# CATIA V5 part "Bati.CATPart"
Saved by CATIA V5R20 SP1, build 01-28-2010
Part number: Bati
Bounding box of the stored display mesh (mm): x -45 to 45, y 0 to 30, z 0 to 40
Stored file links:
  F:\Pro\Emplois\1_Chercheur\ThinkMOTION\MMS\MMS_GR1\abruchon\Catia\Bati.CATPart
  F:\Pro\Emplois\1_Chercheur\ThinkMOTION\MMS\MMS_GR1\abruchon\Catia\Vibrato.CATProduct
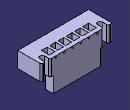
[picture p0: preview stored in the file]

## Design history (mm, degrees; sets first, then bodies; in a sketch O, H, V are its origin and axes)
Set1
  Plane1 to Plane7: linked copy from another document
  Point1: linked copy from another document
  Line1: linked copy from another document
  Line2: linked copy from another document
Body1 (main body)
  Sketch1 on xy-plane, origin (0, 0, 0), H (1, 0, 0), V (0, 1, 0)
    line L1 (-45, 30) -> (45, 30)
    line L2 (45, 30) -> (45, 0)
    line L3 (45, 0) -> (-45, 0)
    line L4 (-45, 0) -> (-45, 30)
    reference intersected line E1 through (0, 30) direction (-1, 0) from Plane1
    reference intersected line E2 through (45, 0) direction (0, 1) from Plane2
    reference intersected line E3 through (-45, 0) direction (0, 1) from Plane3
    reference intersected line E4 through (0, 0) direction (-1, 0) from Plane4
    distance E1 L1 = 0
    distance L2 E2 = 0
    distance E3 L4 = 0
    distance E4 L3 = 0
    horizontal: L1 H, L3 H
    vertical: L2 V, L4 V
  Pad1: profile Sketch1, direction (0, 0, 1), up to Plane5
  Sketch2 on face of Pad1 from Sketch1.L1, origin (0, 30, 0), H (-1, 0, 0), V (0, 0, 1)
    line L1 (-45, 20) -> (-30, 20)
    line L2 (-30, 20) -> (-30, -30)
    line L3 (-30, -30) -> (-45, -30)
    line L4 (-45, -30) -> (-45, 20)
    reference intersected line E1 through (-45, 0) direction (0, -1) from Plane2
    reference intersected line E2 through (-30, 0) direction (0, -1) from Plane6
    point P5 (30, 20)
    line L5 (30, 20) -> (45, 20)
    line L6 (45, 20) -> (45, -30)
    line L7 (45, -30) -> (30, -30)
    line L8 (30, -30) -> (30, 20)
    reference intersected line E3 through (30, 0) direction (0, -1) from Plane7
    reference intersected line E4 through (45, 0) direction (0, -1) from Plane3
    reference projected line E5 (45, 40) -> (-45, 40) from edge [end face of Pad1 | face of Pad1 from Sketch1.L1]
    distance E1 L4 = 0
    distance E2 L2 = 0
    distance E3 L8 = 0
    distance L6 E4 = 0
    distance E5 L5 = 20
    horizontal: L1 H, L3 H, L5 H, L7 H
    vertical: L2 V, L4 V, L6 V, L8 V
    coincidence: P5 L1
  Pocket1: profile Sketch2, direction (0, -1, 0), through (limit type 6)
  Sketch3 on face of Pad1 from Sketch1.L2, origin (45, 0, 0), H (0, 1, 0), V (0, 0, 1)
    line L1 (0, 34.0003) -> (0, 36)
    point P1 (0, 34.0003)
    point P2 (0, 36)
    line L2 (0, 36) -> (1, 35)
    point P3 (1, 35)
    line L3 (0, 34.0003) -> (1, 35)
    reference projected point E1 (1, 35) from Point1
    reference projected line E2 (0, 40) -> (30, 40) from edge [face of Pad1 from Sketch1.L2 | end face of Pad1]
    distance E1 P3 = 0
    distance P2 E2 = 4
    length L3 = 1.414
    length L2 = 1.4142
    coincidence: P1 V
    vertical: L1 V
  Slot1: profile Sketch3, centre curve Line1
  Sketch4 on face of Pad1 from Sketch1.L3, origin (0, 0, 0), H (1, 0, 0), V (0, 0, 1)
    line L1 (30, 30) -> (45, 30)
    line L2 (45, 30) -> (45, 40)
    line L3 (45, 40) -> (30, 40)
    line L4 (30, 40) -> (30, 30)
    reference projected line E1 (45, 0) -> (45, 40) from edge [face of Pad1 from Sketch1.L2 | face of Pad1 from Sketch1.L3]
    reference projected line E2 (30, 20) -> (30, 0) from edge [face of Pad1 from Sketch1.L3 | face of Pocket1 from Sketch2.L2]
    distance E1 L2 = 0
    distance L4 E2 = 0
    horizontal: L1 H, L3 H
    vertical: L2 V, L4 V
  Pad2: profile Sketch4, direction (0, 1, 0), length 9
  Sketch5 on face of Pad2, origin (0, 0, 40), H (1, 0, 0), V (0, 1, 0)
    line L1 (34, 30) -> (40, 30)
    line L2 (40, 30) -> (40, 22.921)
    line L3 (34, 22.921) -> (34, 30)
    reference projected line E1 (45, 0) -> (45, 30) from edge [face of Pad2 | face of Pad2]
    reference projected line E2 (-45, 30) -> (45, 30) from edge [face of Pad2 | face of Pad1 from Sketch1.L1]
    reference projected line E3 (-45, 30) -> (45, 30) from edge [face of Pad2 | face of Pad1 from Sketch1.L1]
    reference projected line E4 (-45, 30) -> (45, 30) from edge [face of Pad2 | face of Pad1 from Sketch1.L1]
    arc A1 centre (37, 22.921) radius 3 from (34, 22.921) to (40, 22.921) ccw
    line L4 (-40, 30) -> (-34, 30)
    line L5 (-34, 30) -> (-34, 22.6056)
    line L6 (-40, 22.6056) -> (-40, 30)
    reference projected line E5 (-45, 30) -> (45, 30) from edge [face of Pad2 | face of Pad1 from Sketch1.L1]
    reference projected line E6 (-45, 30) -> (-45, 0) from edge [face of Pad1 from Sketch1.L4 | face of Pad2]
    arc A2 centre (-37, 22.6056) radius 3 from (-34, 22.6056) to (-40, 22.6056) cw
    distance L2 E1 = 5
    distance E2 E3 = 0 (reference)
    distance E4 L1 = 0
    length L1 = 6
    radius A1 = 3
    distance L4 E5 = 0
    distance L6 E6 = 5
    length L4 = 6
    radius A2 = 3
    length L2 = 7.079
    horizontal: L1 H, L4 H
    vertical: L2 V, L3 V, L5 V, L6 V
  Pocket2: profile Sketch5, direction (0, 0, -1), through (limit type 6)
  Sketch6 on face of Pad2, origin (0, 0, 40), H (1, 0, 0), V (0, 1, 0)
    line L1 (-30, 25) -> (-22.5, 25)
    line L2 (-22.5, 25) -> (-22.5, 15)
    line L3 (-22.5, 15) -> (-30, 15)
    line L4 (-30, 15) -> (-30, 25)
    reference intersected line E1 through (-30, 0) direction (0, 1) from Plane7
    reference intersected line E2 through (-30, 0) direction (0, 1) from Plane7
    reference intersected line E4 through (-30, 0) direction (0, 1) from Plane7
    reference projected line E5 (-45, 30) -> (45, 30) from edge [face of Pad2 | face of Pad1 from Sketch1.L1]
    reference projected line E6 (-45, 30) -> (45, 30) from edge [face of Pad2 | face of Pad1 from Sketch1.L1]
    reference projected line E7 (-45, 30) -> (45, 30) from edge [face of Pad2 | face of Pad1 from Sketch1.L1]
    line L5 (-12, 25) -> (-12, 15)
    line L6 (-12, 15) -> (-19.5, 15)
    line L7 (-19.5, 15) -> (-19.5, 25)
    line L8 (-19.5, 25) -> (-12, 25)
    line L9 (-1.5, 25) -> (-1.5, 15)
    line L10 (-1.5, 15) -> (-9, 15)
    line L11 (-9, 15) -> (-9, 25)
    line L12 (-9, 25) -> (-1.5, 25)
    line L13 (9, 25) -> (9, 15)
    line L14 (9, 15) -> (1.5, 15)
    line L15 (1.5, 15) -> (1.5, 25)
    line L16 (1.5, 25) -> (9, 25)
    line L17 (19.5, 25) -> (19.5, 15)
    line L18 (19.5, 15) -> (12, 15)
    line L19 (12, 15) -> (12, 25)
    line L20 (12, 25) -> (19.5, 25)
    line L21 (30, 25) -> (30, 15)
    line L22 (30, 15) -> (22.5, 15)
    line L23 (22.5, 15) -> (22.5, 25)
    line L24 (22.5, 25) -> (30, 25)
    distance E1 E2 = 0 (reference)
    distance L4 E4 = 0
    distance E5 E6 = 0 (reference)
    distance E7 L1 = 5
    distance L3 L1 = 10
    length L1 = 7.5
    length L8 = 7.5
    distance L6 L8 = 10
    distance L7 E4 = 10.5 (reference)
    distance E7 L8 = 5 (reference)
    distance L10 L12 = 10
    length L12 = 7.5
    distance E7 L12 = 5 (reference)
    distance L11 E4 = 21 (reference)
    distance L14 L16 = 10
    length L16 = 7.5
    distance L15 E4 = 31.5 (reference)
    distance E7 L16 = 5 (reference)
    distance L18 L20 = 10
    length L20 = 7.5
    distance L19 E4 = 42 (reference)
    distance E7 L20 = 5 (reference)
    distance L22 L24 = 10
    length L24 = 7.5
    distance L23 E4 = 52.5 (reference)
    distance E7 L24 = 5 (reference)
    distance L7 L2 = 3
    distance L5 L11 = 3
    distance L9 L15 = 3
    distance L13 L19 = 3
    distance L23 L17 = 3
    horizontal: L1 H, L3 H, L6 H, L8 H, L10 H, L12 H, L14 H, L16 H, L18 H, L20 H, L22 H, L24 H
    vertical: L2 V, L4 V, L7 V, L5 V, L9 V, L11 V, L15 V, L13 V, L17 V, L19 V, L21 V, L23 V
  Pocket3: profile Sketch6, direction (0, 0, -1), length 10
  Fillet1: radius 2, on edge [face of Pad1 from Sketch1.L1 | face of Pad2]
  Fillet2: radius 2, on edge [face of Pad1 from Sketch1.L1 | face of Pocket2 from Sketch5.L2]
  Fillet3: radius 2, on edge [face of Pocket2 from Sketch5.L3 | face of Pad1 from Sketch1.L1]
  Fillet4: radius 2, on edge [face of Pad1 from Sketch1.L1 | face of Pocket2 from Sketch5.L5]
  Fillet5: radius 2, on edge [face of Pocket2 from Sketch5.L6 | face of Pad1 from Sketch1.L1]
  Fillet6: radius 2, on edge [face of Pad1 from Sketch1.L4 | face of Pad1 from Sketch1.L1]
  Sketch7 on face of Pocket1 from Sketch2.L2, origin (30, 0, 0), H (0, 1, 0), V (0, 0, 1)
    line L1 (-10, 20) -> (20, 20)
    line L2 (20, 20) -> (20, -10)
    line L3 (20, -10) -> (-10, -10)
    line L4 (-10, -10) -> (-10, 20)
    reference projected line E1 (30, 20) -> (0, 20) from edge [face of Pad2 | face of Pocket1 from Sketch2.L1]
    reference projected line E2 (30, 0) -> (30, 20) from edge [face of Pad1 from Sketch1.L1 | face of Pocket1 from Sketch2.L2]
    distance E1 L1 = 0
    distance L2 E2 = 10
    horizontal: L1 H, L3 H
    vertical: L2 V, L4 V
  Pocket4: profile Sketch7, direction (-1, 0, 0), through (limit type 6)
  Sketch8 on face of Pad1 from Sketch1.L1, origin (0, 30, 0), H (-1, 0, 0), V (0, 0, 1)
    circle A1 centre (-26.25, 38) radius 1
    point P1 (-26.25, 38)
    reference projected line E1 (-34, 40) -> (-34, 20) from edge [face of Pocket2 from Sketch5.L3 | face of Fillet3]
    reference projected line E2 (45, 40) -> (-45, 40) from edge [face of Pad2 | face of Pad1 from Sketch1.L1]
    point P2 (-15.75, 38)
    circle A2 centre (-15.75, 38) radius 1
    point P3 (-5.25, 38)
    circle A3 centre (-5.25, 38) radius 1
    point P4 (5.25, 38)
    circle A4 centre (5.25, 38) radius 1
    point P5 (15.75, 38)
    circle A5 centre (15.75, 38) radius 1
    point P6 (26.25, 38)
    circle A6 centre (26.25, 38) radius 1
    distance E1 P1 = 7.75
    radius A1 = 1
    distance A1 E2 = 1
    distance P2 P1 = 10.5
    distance P2 P3 = 10.5
    distance P3 P4 = 10.5
    distance P4 P5 = 10.5
    distance P5 P6 = 10.5
  Pocket5: profile Sketch8, direction (0, -1, 0), up to face of Pocket3 from Sketch6.L22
